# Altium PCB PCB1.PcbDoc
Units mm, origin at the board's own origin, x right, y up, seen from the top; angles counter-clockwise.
Board outline 152.4 x 101.6 mm, 2 copper layers (Top Layer, Bottom Layer); 32 components, 47 nets, 140 pads, 12 vias.
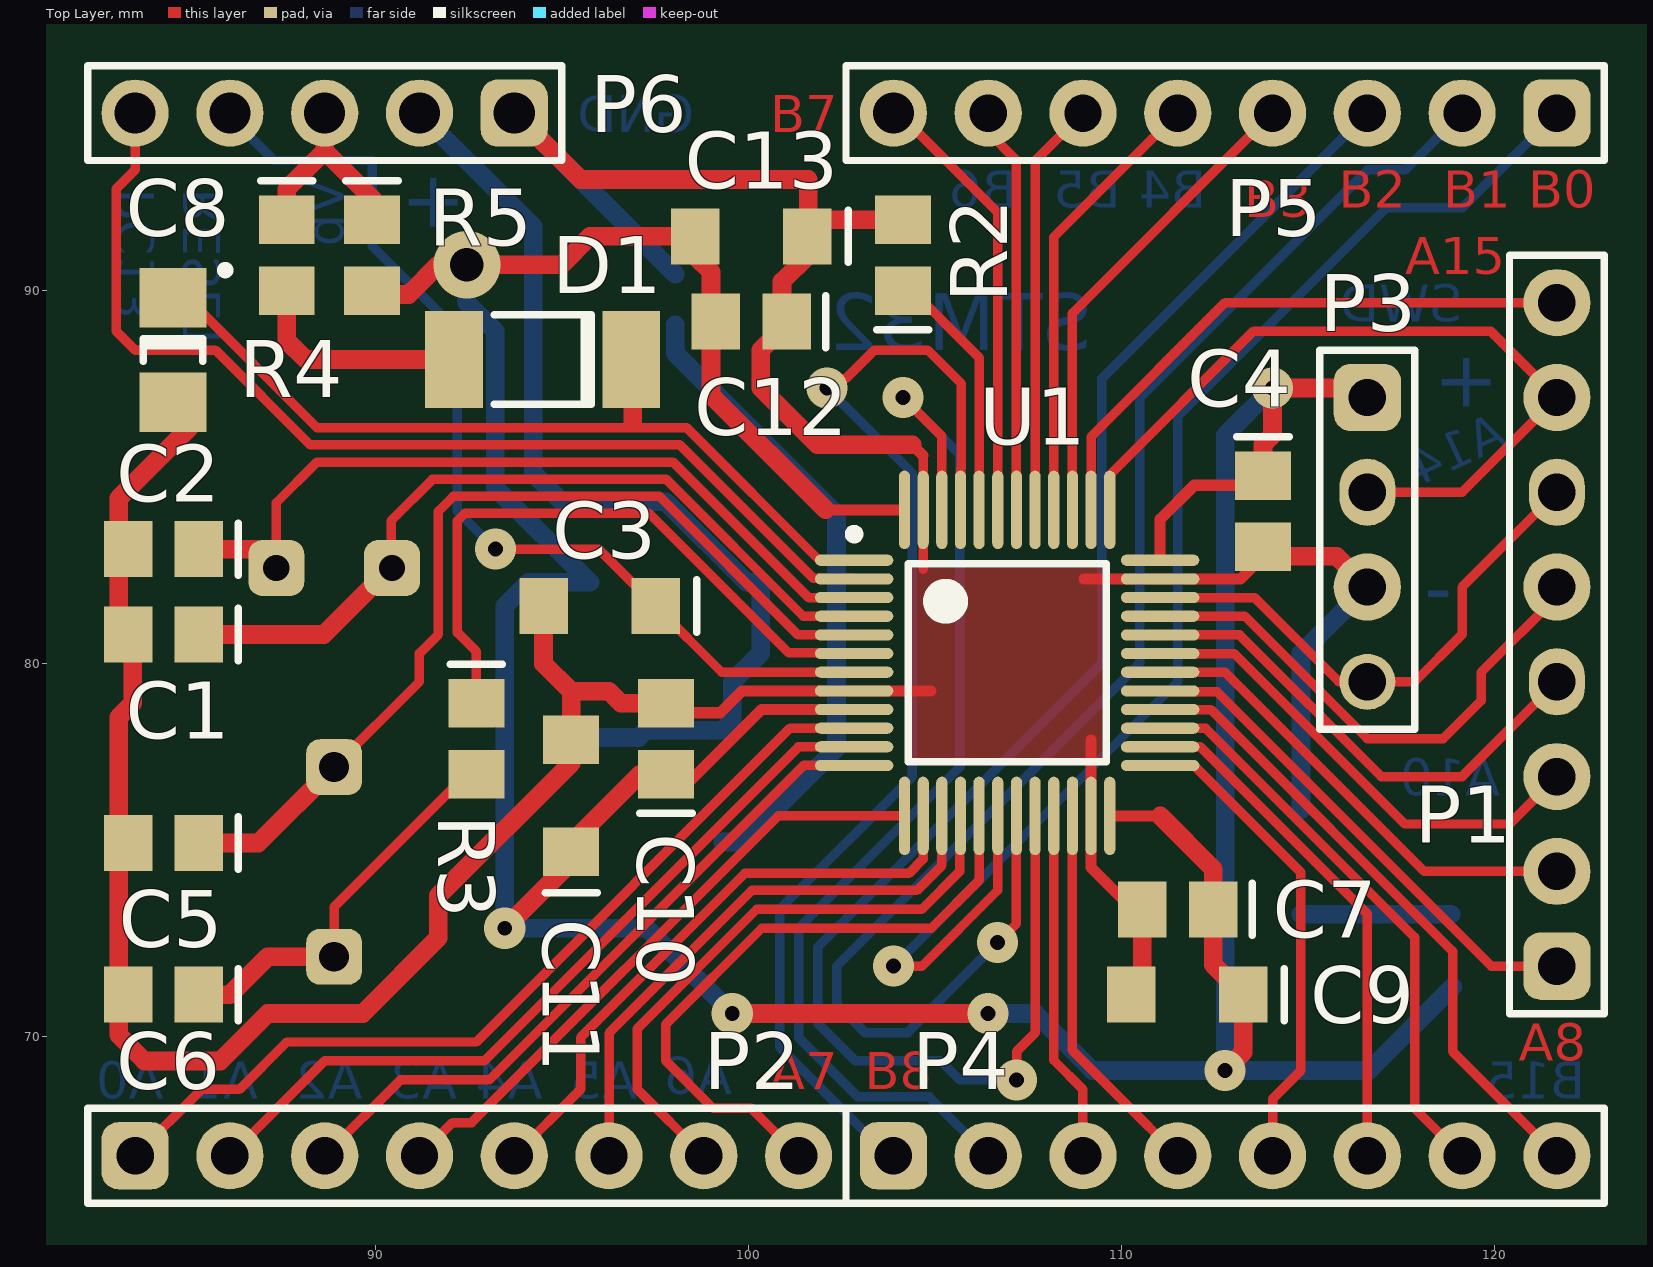
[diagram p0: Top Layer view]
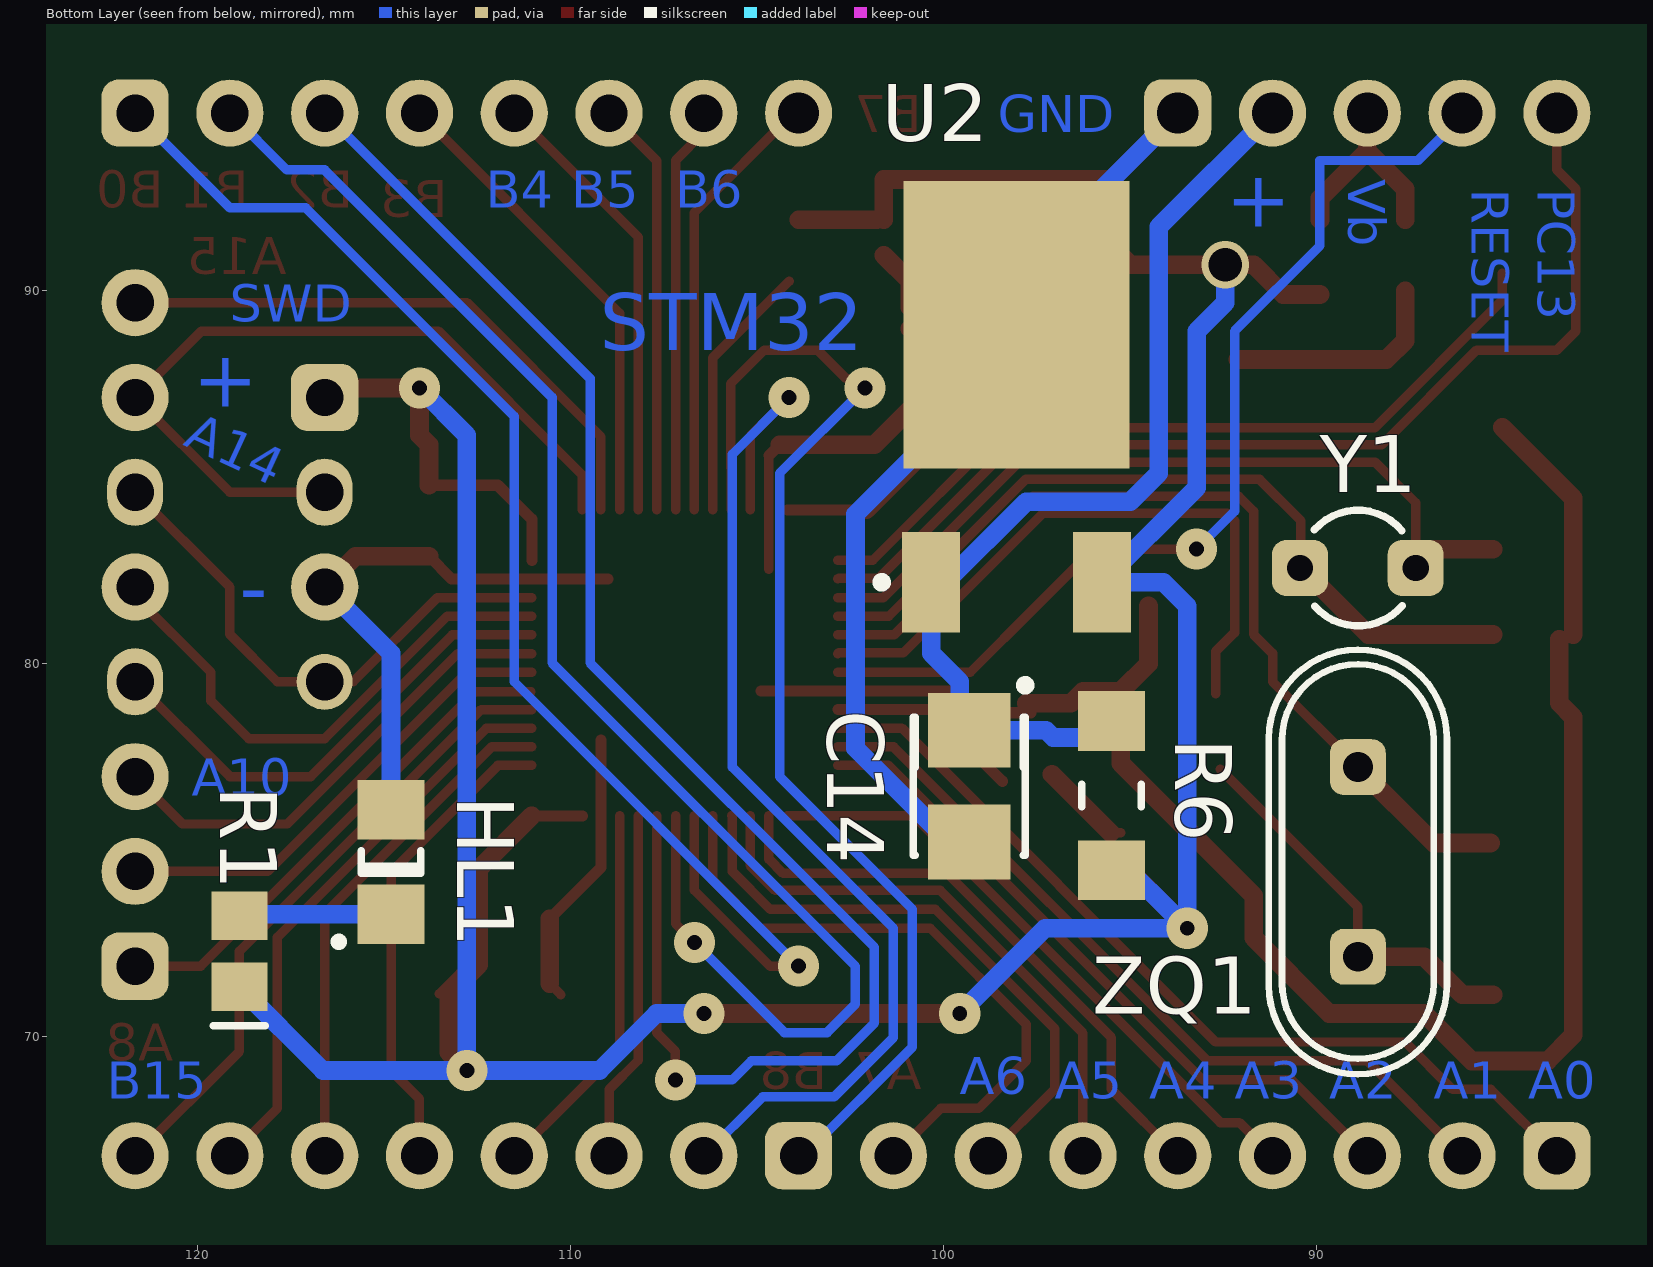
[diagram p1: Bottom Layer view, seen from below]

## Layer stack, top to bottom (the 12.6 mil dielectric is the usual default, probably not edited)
Top Solder: solder mask 0.0102, Solder Resist, Dk 3.5
Top Layer: signal copper 0.0356
Dielectric1: dielectric 0.32, FR-4, Dk 4.8
Bottom Layer: signal copper 0.0356
Bottom Solder: solder mask 0.0102, Solder Resist, Dk 3.5

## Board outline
25.4,25.4 177.8,25.4 177.8,127 25.4,127

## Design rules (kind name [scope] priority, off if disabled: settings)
Clearance [All] p1: gap=0.2
PlaneConnect [All] p1: planeconnectstyle=Relief reliefexpansion=0.254 reliefentries=4 reliefconductorwidth=0.254 reliefairgap=0.254
PolygonConnect [All] p1: connectstyle=Relief reliefconductorwidth=0.254 reliefentries=4 polygonreliefangle="45 Angle" airgapwidth=0.254
RoomDefinition Sheet1 [InComponentClass('Sheet1')] p1: confinementstyle=ConfineIn formatcopy=TRUE lockcomponents=FALSE outline 81.788,65.024 123.444,65.024 123.444,96.52 81.788,96.52
RoutingCorners [All] p1: cornerstyle=Round minsetback=2.54 maxsetback=2.54
RoutingVias [All] p1: holewidth=0.711 width=1.27 viastyle="Through Hole" minholewidth=0.711 minwidth=1.27 maxholewidth=0.711 maxwidth=1.27
SolderMaskExpansion [All] p1: expansion=0.2
UnpouredPolygon [All] p1: allowunpoured=FALSE
Width [All] p1: maxlimit=0.5 minlimit=0.254 preferedwidth=0.3
27 further rules are at their usual default settings.

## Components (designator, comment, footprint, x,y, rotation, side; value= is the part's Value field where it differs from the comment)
C1 "Cap Semi" C0805 84.328,80.772 r180 top
C2 "Cap Semi" C0805 84.328,83.058 r180 top
C3 "Cap Semi" "C0805 - wa" 96.012,81.534 r180 top
C4 "Cap Semi" C0805 113.792,84.074 r270 top
C5 "Cap Semi" C0805 84.328,75.184 r180 top
C6 "Cap Semi" C0805 84.328,71.12 r180 top
C7 "Cap Semi" C0805 111.506,73.406 r180 top
C8 "Cap Semi" C1206 84.582,88.392 r270 top
C9 "Cap Semi" "C0805 - wa" 111.76,71.12 r180 top
C10 "Cap Semi" C0805 97.79,77.978 r90 top
C11 "Cap Semi" "C0805 - wa" 95.25,76.454 r90 top
C12 "Cap Semi" C0805 100.076,89.154 r180 top
C13 "Cap Semi" "C0805 - wa" 100.076,91.44 r180 top
C14 "Cap polar_Vishay Type B" "3528 - Type B" 99.314,76.708 r270 bottom
D1 "1n4148" MELF 94.488,88.138 r0 top
HL1 "S1206YGSC" C1206 114.808,74.676 r90 bottom
P1 "port A 8-15" HDR1X8#1 121.666,71.882 r90 top
P2 "port A 0-7" HDR1X8#2 83.566,66.802 r0 top
P3 "programmer" HDR1X4 116.586,87.122 r270 top
P4 "port B 8-15" HDR1X8#2 103.886,66.802 r0 top
P5 "port B 0-7" HDR1X8#3 121.666,94.742 r180 top
P6 "Header 5" HDR1X5 93.726,94.742 r180 top
R1 "Res2" C0805 118.872,72.281 r90 bottom
R2 "Res2" C0805 104.14,90.932 r90 top
R3 "Res2" C0805 92.71,77.978 r270 top
R4 "Res2" C0805 87.63,90.932 r270 top
R5 "Jumper 0805" C0805 89.916,90.932 r270 top
R6 "Resistor 1206" "1206 - wa" 95.504,76.454 r270 bottom
U1 "STM32F100C8T6B" LQFP48_M 106.934,80.01 r0 top
U2 "" DPAK 98.044,86.868 r90 bottom
Y1 "32768 Hz" R38 88.9,82.55 r90 bottom
ZQ1 "8 MHz" HC49S 88.9,74.675 r90 bottom

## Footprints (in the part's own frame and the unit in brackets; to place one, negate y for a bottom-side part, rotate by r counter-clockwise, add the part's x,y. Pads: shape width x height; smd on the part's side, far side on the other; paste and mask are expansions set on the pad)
"1206 - wa" [mm] "Chip Resistor; Body 3.1 x 1.6 mm (LxW typ)"
  rect 1.6x1.8 smd: 1(-2,0) 2(2,0)
  silkscreen extent -0.3,-0.8 0.3,0.8
"3528 - Type B" [mm] "Capacitor, SM Tantalum; Body 3.5 x 2.8 mm (LxW typ)"
  rect 2x2.2 smd: 1(-1.5,0) 2(1.5,0)
  silkscreen extent -2.82,-1.5 1.85,1.62
C0805 [mm] "Chip Capacitor; Body 2.0 x 1.2 mm (LxW typ)"
  rect 1.3x1.5 smd: 1(-0.95,0) 2(0.95,0)
  silkscreen extent -2,-0.7 -2,0.7
"C0805 - wa" [mm] "Chip Capacitor; Body 2.0 x 1.2 mm (LxW typ)"
  rect 1.3x1.5 smd: 1(-1.5,0) 2(1.5,0)
  silkscreen extent -2.6,-0.7 -2.6,0.7
C1206 [mm] "Chip Capacitor; Body 3.2 x 1.6 mm (LxW typ)"
  rect 1.6x1.8 smd: 1(-1.4,0) 2(1.4,0)
  silkscreen extent -2.18,-0.8 0.3,1.44
DPAK [mm] "D-PAK, 3-Pads, Body 6,2x6,6mm (max), IPC Medium Density"
  rect 2.7x1.55 smd: 1(-4.7,2.29) 3(-4.7,-2.29)
  rect 7.7x6.05 smd: 2(2.2,0)
  silkscreen extent -4.82,3.49 -4.58,3.74, body extent -5.59,-3.3 4.51,3.3, height 2.4
HC49S [mm]
  rrect50% 1.5x1.5 hole 0.8: 1(-2.54,0) 2(2.54,0)
  silkscreen extent -5.69,-2.39 5.69,2.39
HDR1X4 [mm] "Connector; Header; 4 Position"
  rrect50% 1.8x1.8 hole 1: 1(0,0)
  oval 1.8x1.5 hole 1: 2(2.54,0)
  round 1.8 hole 1: 3(5.08,0)
  round 1.5 hole 1: 4(7.62,0)
  silkscreen extent -1.27,-1.27 8.89,1.27
HDR1X5 [mm] "Connector; Header; 5 Position"
  rrect50% 1.8x1.8 hole 1.1: 1(0,0)
  round 1.8 hole 1.1: 2(2.54,0) 3(5.08,0) 4(7.62,0) 5(10.16,0)
  silkscreen extent -1.27,-1.27 11.43,1.27
HDR1X8#1 [mm] "Connector; Header; 8 Position"
  rrect50% 1.8x1.8 hole 1: 1(0,0)
  round 1.8 hole 1: 2(2.54,0) 3(5.08,0) 5(10.16,0) 7(15.24,0) 8(17.78,0)
  oval 1.8x1.5 hole 1: 4(7.62,0) 6(12.7,0)
  silkscreen extent -1.27,-1.27 19.05,1.27
HDR1X8#2 [mm] "Connector; Header; 8 Position"
  rrect50% 1.8x1.8 hole 1: 1(0,0)
  round 1.8 hole 1: 2(2.54,0) 3(5.08,0) 4(7.62,0) 5(10.16,0) 6(12.7,0) 7(15.24,0) 8(17.78,0)
  silkscreen extent -1.27,-1.27 19.05,1.27
HDR1X8#3 [mm] "Connector; Header; 8 Position"
  rrect50% 1.8x1.8 hole 1: 1(0,0)
  round 1.8 hole 1: 2(2.54,0) 3(5.08,0) 4(7.62,0) 5(10.16,0) 6(12.7,0) 7(15.24,0)
  round 1.8 hole 1.1: 8(17.78,0)
  silkscreen extent -1.27,-1.27 19.05,1.27
LQFP48_M [mm] "Thin QFP, 48-Leads, Body 7x7mm, Pitch 0.5mm, IPC Low Density"
  oval 2.1x0.3 smd: 1(-4.1,2.75) 2(-4.1,2.25) 3(-4.1,1.75) 4(-4.1,1.25) 5(-4.1,0.75) 6(-4.1,0.25) 7(-4.1,-0.25) 8(-4.1,-0.75) 9(-4.1,-1.25) 10(-4.1,-1.75) 11(-4.1,-2.25) 12(-4.1,-2.75) 25(4.1,-2.75) 26(4.1,-2.25) 27(4.1,-1.75) 28(4.1,-1.25) 29(4.1,-0.75) 30(4.1,-0.25) 31(4.1,0.25) 32(4.1,0.75) 33(4.1,1.25) 34(4.1,1.75) 35(4.1,2.25) 36(4.1,2.75)
  oval 0.3x2.1 smd: 13(-2.75,-4.1) 14(-2.25,-4.1) 15(-1.75,-4.1) 16(-1.25,-4.1) 17(-0.75,-4.1) 18(-0.25,-4.1) 19(0.25,-4.1) 20(0.75,-4.1) 21(1.25,-4.1) 22(1.75,-4.1) 23(2.25,-4.1) 24(2.75,-4.1) 37(2.75,4.1) 38(2.25,4.1) 39(1.75,4.1) 40(1.25,4.1) 41(0.75,4.1) 42(0.25,4.1) 43(-0.25,4.1) 44(-0.75,4.1) 45(-1.25,4.1) 46(-1.75,4.1) 47(-2.25,4.1) 48(-2.75,4.1)
  silkscreen extent -4.22,-2.65 2.65,3.57, body extent -3.5,-3.5 3.5,3.5, height 1.6
MELF [mm] "Metal Electrode Face (MELF) Diode; Body 5 x 2.5 mm (LxDia)"
  rect 1.55x2.6 smd: 1(-2.375,0) 2(2.375,0)
  silkscreen extent -1.3,-1.2 1.3,1.2
R38 [mm] "Crystal, Thru-Hole; 2 Leads; Body 3.1 x 8.2 mm (Dia.xH)"
  rrect50% 1.5x1.5 hole 0.7: 1(0,1.55) 2(0,-1.55)
  silkscreen extent -1.55,-1.19 1.55,1.17

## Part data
C1 C2 C3 C4 C5 C6 C7 C8 C9 C10 C11 C12 C13: "Capacitor (Semiconductor SIM Model)"
C14: "Capacitor (Model Sergeev)"
D1: library part SM4001, "Диод SMD 1A, 1000V"
HL1: library part "LED CMD", "Typical INFRARED GaAs LED"
P1 P2 P4 P5: library part "Header 8", "Header, 8-Pin"
P3: library part "Header 4", "Header, 4-Pin"
P6: "Header, 5-Pin"
R1 R2 R3 R4: "Resistor"
R5: library part "Resistor 0805"
U1: "STM32 ARM-based 32-bit MCU Value Line with 64 kB Flash, 8 kB Internal RAM, Internal Code B, -40 to +85°C Temperature, 48-Pin LQFP, Tray"
U2: library part L7805ABV, "Precision 1A Regulator"
Y1 ZQ1: library part XTAL, "Crystal Oscillator"

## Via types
v1: diameter 1.1, hole 0.4, Top Layer to Bottom Layer, tented both sides, 11 vias
v2: diameter 1.8/1.27 (per signal layer), hole 0.9, Top Layer to Bottom Layer, 1 vias

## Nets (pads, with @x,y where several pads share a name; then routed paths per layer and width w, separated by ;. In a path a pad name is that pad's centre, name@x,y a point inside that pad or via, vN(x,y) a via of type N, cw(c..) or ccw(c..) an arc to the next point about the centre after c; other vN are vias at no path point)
GND: C1.2 C2.2 C3.2 C4.2 C5.2 C6.2 C7.2 C8.2 C9.2 C10.2 C11.2 C12.1 C13.1 C14.2 HL1.2 P3.3 P6.1 R2.2 U1.8 U1.23 U1.35 U1.47 U2.2 | length 117.9
  Top Layer w0.254: C12.1@100.899,88.961 C12.1@100.899,89.535 ; 104.681,85.565 104.681,84.113 U1.47 104.684,82.514 ; C9.2 C9.2@110.556,71.416
  Top Layer w0.3: C10.2@97.663,78.674 99.248,78.674 99.834,79.26 U1.8 104.89,79.26 ; 104.394,85.852 104.681,85.565 ; 109.002,82.26 U1.35 113.182,82.26 C4.2@113.792,82.87 ; 109.184,77.942 U1.23 109.184,74.524 C7.2@110.556,73.152
  Top Layer w0.5: C1.2@83.124,80.772 83.124,84.418 C8.2@85.033,86.328 ; C1.2@83.505,80.645 83.505,78.933 83.124,78.552 83.124,70.038 83.82,69.342 85.852,69.342 87.122,70.612 89.662,70.612 91.694,72.644 91.694,73.768 95.25,77.324 C11.2 95.25,79.248 ; P6.1 95.504,92.964 101.6,92.964 C13.1@101.6,91.882 ; C3.2 94.512,79.986 95.25,79.248 ; C10.2 96.586,78.928 96.266,79.248 95.25,79.248 ; C12.1@100.899,88.961 100.33,88.392 100.33,87.376 101.854,85.852 104.394,85.852 ; C12.1@100.899,89.535 100.899,90.231 C13.1@101.6,90.932 ; C13.1@101.788,91.882 R2.2@103.886,91.882 ; C9.2@110.556,71.416 C7.2@110.556,73.152 ; C4.2@113.792,82.87 115.758,82.87 P3.3
  Bottom Layer w0.5: P6.1 U2.2@98.044,90.424 ; U2.2 98.044,88.31 102.362,83.992 102.362,77.724 99.846,75.208 C14.2 ; HL1.2 114.808,80.264 P3.3
NetC1_1: C1.1 U1.4 Y1.1 | length 21.5
  Top Layer w0.254: Y1.1@90.424,82.576 90.424,83.82 91.532,84.928 97.804,84.928 101.472,81.26 U1.4
  Top Layer w0.5: C1.1 88.62,80.772 Y1.1@90.424,82.576
NetC2_1: C2.1 U1.3 Y1.2 | length 21.5
  Top Layer w0.254: Y1.2@86.842,83.058 Y1.2 87.35,84.302 88.43,85.382 97.992,85.382 101.614,81.76 U1.3
  Top Layer w0.5: C2.1 Y1.2@86.842,83.058
NetC3_1: C3.1 P6.4 U1.7 | length 27.2
  Top Layer w0.254: v1(93.218,83.058) 95.988,83.058 C3.1 99.286,79.76 U1.7
  Bottom Layer w0.254: P6.4 86.106,94.652 87.286,93.472 89.916,93.472 89.916,91.186 92.202,88.9 92.202,84.074 v1(93.218,83.058)
NetC4_1: C4.1 C7.1 C9.1 C10.1 C11.1 C12.2 C13.2 P3.1 R1.1 R6.2 U1.9 U1.24 U1.36 U1.48 U2.3 | length 120.2
  Top Layer w0.254: C11.1@95.25,75.462 C11.1@95.528,75.462 ; C9.1@112.964,71.694 C9.1@113.514,71.144
  Top Layer w0.3: C10.1@98.425,76.835 100.35,78.76 U1.9 ; 102.072,84.11 U1.48 ; U1.24 111.034,75.91 ; U1.36 111.034,83.856 111.948,84.77 C4.1@113.792,84.77
  Top Layer w0.5: 89.916,89.882 90.898,89.882 91.694,90.678 v2(92.456,90.678) 94.996,90.678 95.758,91.44 C13.2 ; v1(93.472,72.898) C11.1@95.25,74.676 ; C11.1@95.528,75.462 C10.1@97.094,77.028 ; C13.2@98.576,90.908 98.999,90.485 98.999,87.183 102.072,84.11 ; v1(99.568,70.612) v1(106.426,70.612) ; 111.034,75.91 112.456,74.488 112.456,71.924 C9.1 113.26,69.572 v1(112.776,69.088) ; C4.1@113.792,84.77 113.792,85.852 114.046,86.106 v1(114.046,87.376) 116.332,87.376 P3.1
  Bottom Layer w0.5: v2(92.456,90.678) 92.456,89.662 93.218,88.9 93.218,84.704 U2.3 94.106,82.168 93.472,81.534 v1(93.472,72.898) ; R6.2@95.504,74.93 v1(93.472,72.898) ; v1(99.568,70.612) 97.282,72.898 v1(93.472,72.898) ; v1(106.426,70.612) 107.696,70.612 109.22,69.088 v1(112.776,69.088) ; v1(114.046,87.376) 112.776,86.106 v1(112.776,69.088) ; R1.1 116.629,69.088 v1(112.776,69.088)
NetC5_1: C5.1 U1.5 ZQ1.2 | length 25.3
  Top Layer w0.254: ZQ1.2 91.186,79.502 91.186,80.264 91.694,80.772 91.694,84.074 92.094,84.474 97.616,84.474 101.33,80.76 U1.5
  Top Layer w0.5: C5.1@85.344,75.184 86.868,75.184 ZQ1.2
NetC6_1: C6.1 R3.2 ZQ1.1 | length 10.6
  Top Layer w0.254: ZQ1.1 88.9,73.472 R3.2@92.583,77.155
  Top Layer w0.5: C6.1 86.106,71.12 87.122,72.136 ZQ1.1
NetC8_1: C8.1 D1.2 U1.1 | length 24.9
  Top Layer w0.254: C8.1@85.034,90.456 85.034,89.718 88.446,86.306 96.774,86.306 ; D1.2@96.774,88.049 96.774,86.306 ; D1.2@97.028,88.049 97.028,86.306 ; U1.1 101.898,82.76 98.352,86.306 97.028,86.306 ; 96.774,86.306 97.028,86.306
NetC14_1: C14.1 P6.2 R6.1 U2.1 | length 26.5
  Bottom Layer w0.5: P6.2 94.234,91.694 94.234,85.09 94.996,84.328 97.79,84.328 99.95,82.168 U2.1 100.334,80.268 99.568,79.502 99.568,78.462 C14.1 97.258,78.208 97.062,78.012 R6.1@95.504,78.012
NetD1_1: D1.1 R4.2 | length 6
  Top Layer w0.5: R4.2 87.63,88.646 88.138,88.138 D1.1
NetHL1_1: HL1.1 R1.2 | length 4
  Bottom Layer w0.5: HL1.1 R1.2@118.827,73.276
NetP1_1: P1.1 U1.29 | length 13.7
  Top Layer w0.254: U1.29@111.057,79.237 112.558,79.237 119.913,71.882 P1.1
NetP1_2: P1.2 U1.30 | length 12.8
  Top Layer w0.254: U1.30 112.772,79.76 118.11,74.422 P1.2
NetP1_3: P1.3 U1.31 | length 13.1
  Top Layer w0.254: U1.31 113.02,80.26 117.588,75.692 120.396,75.692 P1.3
NetP1_4: P1.4 U1.32 | length 13.3
  Top Layer w0.254: U1.32 113.162,80.76 116.96,76.962 119.126,76.962 P1.4
NetP1_5: P1.5 U1.33 | length 14
  Top Layer w0.254: U1.33 113.304,81.26 116.586,77.978 118.618,77.978 119.634,78.994 119.634,79.757 P1.5@121.666,81.789
NetP1_6: P1.6 P3.4 U1.34 | length 14.4
  Top Layer w0.254: U1.34 113.566,81.76 115.824,79.502 117.856,79.502 119.126,80.772 119.126,82.042 P1.6
NetP1_7: P1.7 P3.2 U1.37 | length 21.4
  Top Layer w0.254: U1.37 109.684,85.046 113.538,88.9 119.888,88.9 P1.7 119.126,84.582 P3.2
NetP1_8: P1.8 U1.38 | length 15.9
  Top Layer w0.254: U1.38 109.184,86.07 112.776,89.662 P1.8
NetP2_1: P2.1 U1.10 | length 24
  Top Layer w0.254: P2.1 85.344,68.58 86.36,68.58 87.63,69.85 92.71,69.85 101.12,78.26 U1.10
NetP2_2: P2.2 U1.11 | length 21.3
  Top Layer w0.254: P2.2 88.646,69.342 92.922,69.342 101.34,77.76 U1.11
NetP2_3: P2.3 U1.12 | length 18.5
  Top Layer w0.254: P2.3 90.678,68.834 93.056,68.834 101.482,77.26 U1.12
NetP2_4: P2.4 U1.13 | length 16.8
  Top Layer w0.254: P2.4 92.075,67.691 92.583,67.691 100.802,75.91 U1.13
NetP2_5: P2.5 U1.14 | length 16.2
  Top Layer w0.254: P2.5 95.504,68.58 95.504,69.97 99.902,74.368 104.302,74.368 104.684,74.75 U1.14
NetP2_6: P2.6 U1.15 | length 15.4
  Top Layer w0.254: P2.6 96.266,70.09 100.09,73.914 104.514,73.914 105.184,74.584 U1.15
NetP2_7: P2.7 U1.16 | length 16
  Top Layer w0.254: P2.7 97.028,68.58 97.028,70.21 100.224,73.406 104.648,73.406 105.661,74.419 105.661,75.887 U1.16
NetP2_8: P2.8 U1.17 | length 17.3
  Top Layer w0.254: P2.8 100.076,68.072 99.06,68.072 97.79,69.342 97.79,70.33 100.358,72.898 104.902,72.898 106.184,74.18 U1.17
NetP4_1: P4.1 U1.45 | length 32
  Top Layer w0.254: v1@102.108,87.63 102.616,87.63 103.378,88.392 104.806,88.392 105.71,87.488 105.71,85.239 105.687,85.216 U1.45@105.687,84.113
  Bottom Layer w0.254: v1(102.108,87.376) 104.394,85.09 104.394,76.962 100.838,73.406 100.838,69.716 103.752,66.802 P4.1
NetP4_2: P4.2 U1.46 | length 29.4
  Top Layer w0.254: v1(104.14,87.122) 105.184,86.078 U1.46
  Bottom Layer w0.254: v1(104.14,87.122) 105.664,85.598 105.664,77.216 101.346,72.898 101.346,69.97 102.936,68.38 104.848,68.38 P4.2
NetP4_3: P4.3 U1.21 | length 9.4
  Top Layer w0.254: U1.21 108.184,69.362 108.966,68.58 P4.3
NetP4_4: P4.4 U1.22 | length 10.3
  Top Layer w0.254: U1.22 108.684,69.624 109.982,68.326 P4.4
NetP4_5: P4.5 U1.25 | length 12.9
  Top Layer w0.254: U1.25 111.942,77.26 114.808,74.394 114.808,69.088 114.046,68.326 P4.5
NetP4_6: P4.6 U1.26 | length 13.9
  Top Layer w0.254: U1.26 111.037,77.757 112.112,77.757 116.586,73.283 P4.6
NetP4_7: P4.7 U1.27 | length 15.5
  Top Layer w0.254: U1.27 111.037,78.257 112.254,78.257 117.856,72.655 117.856,68.072 P4.7
NetP4_8: P4.8 U1.28 | length 17.2
  Top Layer w0.254: U1.28 111.037,78.757 112.396,78.757 118.872,72.281 118.872,69.596 P4.8
NetP5_1: P5.1 U1.18 | length 37
  Top Layer w0.254: v1(103.886,71.882) 104.648,71.882 106.684,73.918 U1.18
  Bottom Layer w0.254: v1(103.886,71.882) 111.506,79.502 111.506,86.614 117.094,92.202 119.126,92.202 P5.1
NetP5_2: P5.2 U1.19 | length 41
  Top Layer w0.254: v1@106.68,72.136 v1(106.68,72.517) 107.184,73.021 U1.19
  Bottom Layer w0.254: v1(106.68,72.517) 104.267,70.104 103.124,70.104 102.362,70.866 102.362,71.882 110.49,80.01 110.49,87.122 116.586,93.218 117.602,93.218 P5.2
NetP5_3: P5.3 U1.20 | length 43.7
  Top Layer w0.254: v1(107.188,68.834) 107.188,69.596 107.684,70.092 U1.20
  Bottom Layer w0.254: v1(107.188,68.834) 105.664,68.834 105.156,69.342 102.87,69.342 101.854,70.358 101.854,72.39 109.474,80.01 109.474,87.63 P5.3
NetP5_4: P5.4 U1.39 | length 12.9
  Top Layer w0.254: U1.39 108.684,89.38 P5.4
NetP5_5: P5.5 U1.40 | length 12
  Top Layer w0.254: U1.40 108.184,91.42 P5.5
NetP5_6: P5.6 U1.41 | length 11.2
  Top Layer w0.254: U1.41 107.684,93.46 P5.6
NetP5_7: P5.7 U1.42 | length 10.9
  Top Layer w0.254: P5.7 106.426,94.234 107.184,93.476 U1.42
NetP5_8: P5.8 U1.43 | length 11.9
  Top Layer w0.254: P5.8 104.02,94.742 106.684,92.078 U1.43
NetP6_3: P6.3 R4.1 R5.1 | length 5.7
  Top Layer w0.5: R4.1 87.63,92.71 88.646,93.726 ; P6.3 88.646,93.726 ; R5.1 89.916,92.456 88.646,93.726
NetP6_5: P6.5 U1.2 | length 28.6
  Top Layer w0.254: P6.5 83.566,93.218 83.058,92.71 83.058,88.9 83.566,88.392 85.718,88.392 88.258,85.852 98.164,85.852 101.733,82.283 102.811,82.283 U1.2
NetR2_1: R2.1 U1.44 | length 7
  Top Layer w0.254: R2.1@104.14,90.236 106.184,88.192 U1.44
NetR3_1: R3.1 U1.6 | length 17.1
  Top Layer w0.254: R3.1@92.71,79.182 92.71,80.315 92.202,80.823 92.202,83.82 92.402,84.02 97.336,84.02 101.076,80.28 102.814,80.28 U1.6
pads on no net: R5.2

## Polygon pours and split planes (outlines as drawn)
GND on Top Layer "Top Layer-No Net" (solid, pour order 11): 104.394,82.55 109.474,82.55 109.474,77.47 104.394,77.47

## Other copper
Top Layer:
  text "B7" at 100.584,94.234 h1
  text "B2" at 115.824,92.202 h1
  text "B1" at 118.618,92.202 h1
  text "B0" at 120.904,92.202 h1
  text "B3" at 113.284,91.948 h1
  text "A15" at 117.602,90.424 h1
  text "A8" at 120.65,69.342 h1
  text "A7" at 100.584,68.58 h1
  text "B8" at 103.124,68.58 h1
Bottom Layer:
  text "GND" at 98.552,94.234 h1
  text "Vb" at 89.154,92.964 h1 r90
  text "PC13" at 84.074,92.71 h1 r90
  text "RESET" at 85.852,92.71 h1 r90
  text "B6" at 107.188,92.202 h1
  text "B5" at 109.982,92.202 h1
  text "B4" at 112.268,92.202 h1
  text "+" at 90.678,91.694 h1.52
  text "SWD" at 119.126,89.154 h1
  text "STM32" at 109.22,88.392 h1.52
  text "+" at 118.364,86.868 h1.52
  text "A14" at 120.396,85.852 h1 r24.77
  text "-" at 118.11,81.28 h1.52
  text "A10" at 120.142,76.454 h1
  text "A6" at 99.568,68.446 h1
  text "A0" at 84.328,68.326 h1
  text "A1" at 86.868,68.326 h1
  text "A2" at 89.662,68.326 h1
  text "A3" at 92.202,68.326 h1
  text "A4" at 94.488,68.326 h1
  text "A5" at 97.028,68.326 h1
  text "B15" at 122.428,68.326 h1

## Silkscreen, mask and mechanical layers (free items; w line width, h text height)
Mechanical 1:
  lines w0.2: 82.042,65.278 123.19,65.278 123.19,96.266 122.936,96.266 82.042,96.266 82.042,70.928 82.042,65.278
